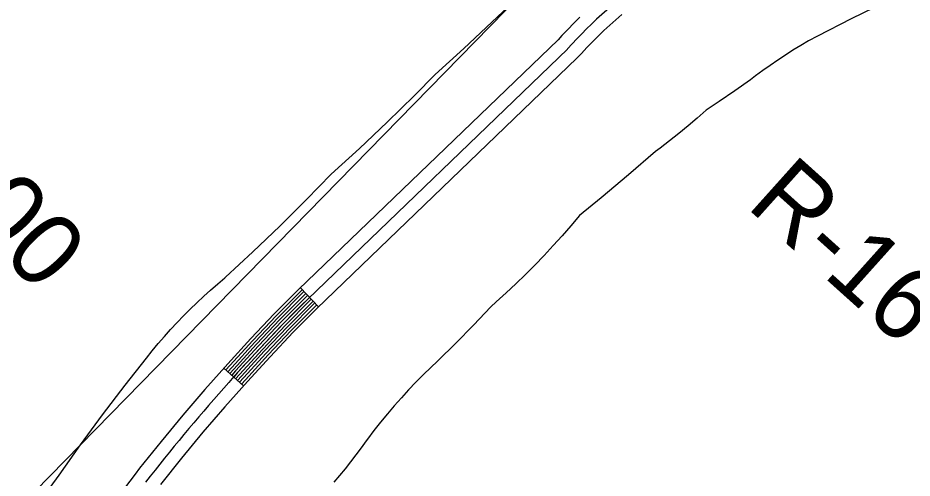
# Model space of a CAD drawing. Extents: x 3180038 to 3217926, y 922069 to 947485.
# Drawn here: x 3194927 to 3195944, y 936834 to 937357 of the extents above; entities that cross this region are included whole.
import ezdxf

# ---------------------------------------------------------------- set-up
doc = ezdxf.new("R2010")
doc.units = 0
for name, color, linetype in [('V-LEVE-TOET', 7, 'Continuous'), ('V-RIVR-RANG-IDEN', 7, 'Continuous'), ('V-ROAD-CNTR', 7, 'Continuous'), ('V-SITE-VEGE', 7, 'Continuous')]:
    doc.layers.add(name, color=color, linetype=linetype)

msp = doc.modelspace()

# ---------------------------------------------------------------- linework, layer by layer
at = {"layer": 'V-LEVE-TOET'}
for points in [[(3195401.7, 937292.6), (3195434.3, 937322), (3195466.4, 937351.9), (3195497.9, 937382.4)], [(3195913.7, 937374.6), (3195874.9, 937355.7), (3195836.5, 937336.2), (3195826.2, 937330.8), (3195826.2, 937330.8), (3195817.4, 937325.5), (3195808.6, 937320.1), (3195800, 937314.5), (3195791.4, 937308.8), (3195782.9, 937302.9), (3195774.5, 937296.9), (3195766.2, 937290.8), (3195760.3, 937286.3), (3195760.3, 937286.3), (3195742.5, 937274.1), (3195724.6, 937262), (3195709.8, 937251.9), (3195709.8, 937251.9), (3195699.7, 937243), (3195689.4, 937234.2), (3195678.9, 937225.5), (3195668.3, 937217.1), (3195657.5, 937208.8), (3195652.3, 937204.9), (3195652.3, 937204.9), (3195621.7, 937178.5), (3195590.7, 937152.5), (3195565.9, 937132.4), (3195565.9, 937132.4), (3195556.2, 937120.8), (3195546.2, 937109.4), (3195536.1, 937098.1), (3195525.8, 937087), (3195515.2, 937076.1), (3195504.5, 937065.3), (3195493.7, 937054.8), (3195482.6, 937044.4), (3195471.3, 937034.2), (3195465.1, 937028.8), (3195465.1, 937028.8), (3195445.4, 937007.9), (3195425.3, 936987.4), (3195404.8, 936967.3), (3195388.4, 936951.6), (3195388.4, 936951.6), (3195379.9, 936943), (3195371.6, 936934.2), (3195363.4, 936925.2), (3195355.3, 936916.1), (3195347.4, 936906.9), (3195339.7, 936897.5), (3195332.1, 936888.1), (3195324.7, 936878.4), (3195323.2, 936876.5), (3195323.2, 936876.5), (3195317.5, 936868.4), (3195311.6, 936860.4), (3195305.5, 936852.6), (3195299.4, 936844.8), (3195293.1, 936837.2), (3195286.7, 936829.6)], [(3194953.9, 936809.3), (3194974.1, 936837.3), (3194974.1, 936837.3), (3194998.6, 936871.9), (3195023.7, 936906.1), (3195049.3, 936939.8), (3195073.5, 936970.5), (3195073.5, 936970.5), (3195080.1, 936978.8), (3195087, 936986.9), (3195093.9, 936995), (3195101, 937002.9), (3195108.3, 937010.7), (3195115.7, 937018.4), (3195123.2, 937025.9), (3195130.8, 937033.3), (3195138.6, 937040.6), (3195146.5, 937047.7), (3195154.5, 937054.7), (3195162.7, 937061.6), (3195163.4, 937062.2), (3195163.4, 937062.2), (3195194.6, 937091.1), (3195225.3, 937120.4), (3195255.4, 937150.4), (3195283.6, 937179.2), (3195283.6, 937179.2), (3195315.6, 937208.5), (3195347.1, 937238.4), (3195378.2, 937268.8), (3195401.7, 937292.6)]]:
    msp.add_lwpolyline(points, dxfattribs=at)
at = {"layer": 'V-ROAD-CNTR'}
for p, q in [((3195269.3, 937028.6), (3195248.5, 937050.3)), ((3195183.9, 936938.9), (3195161.5, 936958.9))]:
    msp.add_line(p, q, dxfattribs=at)
for points in [[(3195566.2, 937357.6), (3195559.3, 937350.8), (3195552.6, 937343.8), (3195545.9, 937336.8), (3195541.5, 937331.9), (3195246.4, 937048.2), (3195218.9, 937020.6), (3195192.2, 936992.5), (3195166, 936963.9), (3195140, 936934.9), (3195114.7, 936905.4), (3195090.1, 936875.6), (3195065.7, 936845.3), (3195060.6, 936838.6), (3194276.3, 935811)], [(3195614.2, 937360.7), (3195607.2, 937354.7), (3195600.4, 937348.6), (3195593.7, 937342.4), (3195587.1, 937336.1), (3195580.6, 937329.7), (3195574.3, 937323.1), (3195568, 937316.4), (3195563, 937311), (3195267.4, 937026.9), (3195240.4, 936999.7), (3195214.1, 936972), (3195188.3, 936943.8), (3195162.6, 936915.2), (3195137.7, 936886.1), (3195113.4, 936856.6), (3195089.3, 936826.8)], [(3195552.3, 937321.4), (3195256.9, 937037.5)], [(3195250.5, 937048.1), (3195248.5, 937046.1), (3195221, 937018.5), (3195194.4, 936990.4), (3195168.3, 936961.9), (3195163.8, 936956.9)], [(3195252.6, 937045.9), (3195250.6, 937044), (3195223.2, 937016.4), (3195196.6, 936988.4), (3195170.5, 936959.9), (3195166, 936954.9)], [(3195254.7, 937043.8), (3195252.7, 937041.8), (3195225.3, 937014.3), (3195198.8, 936986.3), (3195172.7, 936957.9), (3195168.2, 936952.9)], [(3195256.8, 937041.6), (3195254.8, 937039.7), (3195227.5, 937012.2), (3195201, 936984.3), (3195174.9, 936955.9), (3195170.5, 936950.9)], [(3195258.9, 937039.4), (3195256.9, 937037.5), (3195229.6, 937010.1), (3195203.1, 936982.2), (3195177.1, 936953.9), (3195172.7, 936948.9)], [(3195260.9, 937037.3), (3195259, 937035.4), (3195231.8, 937008), (3195205.3, 936980.2), (3195179.4, 936951.9), (3195174.9, 936946.9)], [(3195263, 937035.1), (3195261.1, 937033.3), (3195233.9, 937005.9), (3195207.5, 936978.1), (3195181.6, 936949.8), (3195177.2, 936944.9)], [(3195265.1, 937033), (3195263.2, 937031.1), (3195236.1, 937003.9), (3195209.7, 936976.1), (3195183.8, 936947.8), (3195179.4, 936942.9)], [(3195267.2, 937030.8), (3195265.3, 937029), (3195238.2, 937001.8), (3195211.9, 936974), (3195186, 936945.8), (3195181.6, 936940.9)]]:
    msp.add_lwpolyline(points, dxfattribs=at)
for centre, radius, start, end in [((3195952.9, 936961.2), 538.8, 111.2929, 138.0377), ((3196814.9, 935471.1), 2209.3, 134.8468, 142.0614)]:
    msp.add_arc(centre, radius, start, end, dxfattribs=at)
at = {"layer": 'V-SITE-VEGE'}
msp.add_lwpolyline([(3195426.8, 937406.7), (3195428.4, 937407.8), (3195431.6, 937408.4), (3195533.3, 937418.1), (3194946.6, 936818.9)], dxfattribs=at)

# ---------------------------------------------------------------- texts
at = {"layer": 'V-RIVR-RANG-IDEN'}
for s, rotation, p in [('R-25+00', 313.1806, (3194657, 937355.5)), ('R-16+00', 318.1006, (3195754.3, 937142.4))]:
    msp.add_text(s, height=83, rotation=rotation, dxfattribs=at).set_placement(p)

doc.saveas('drawing.dxf')
